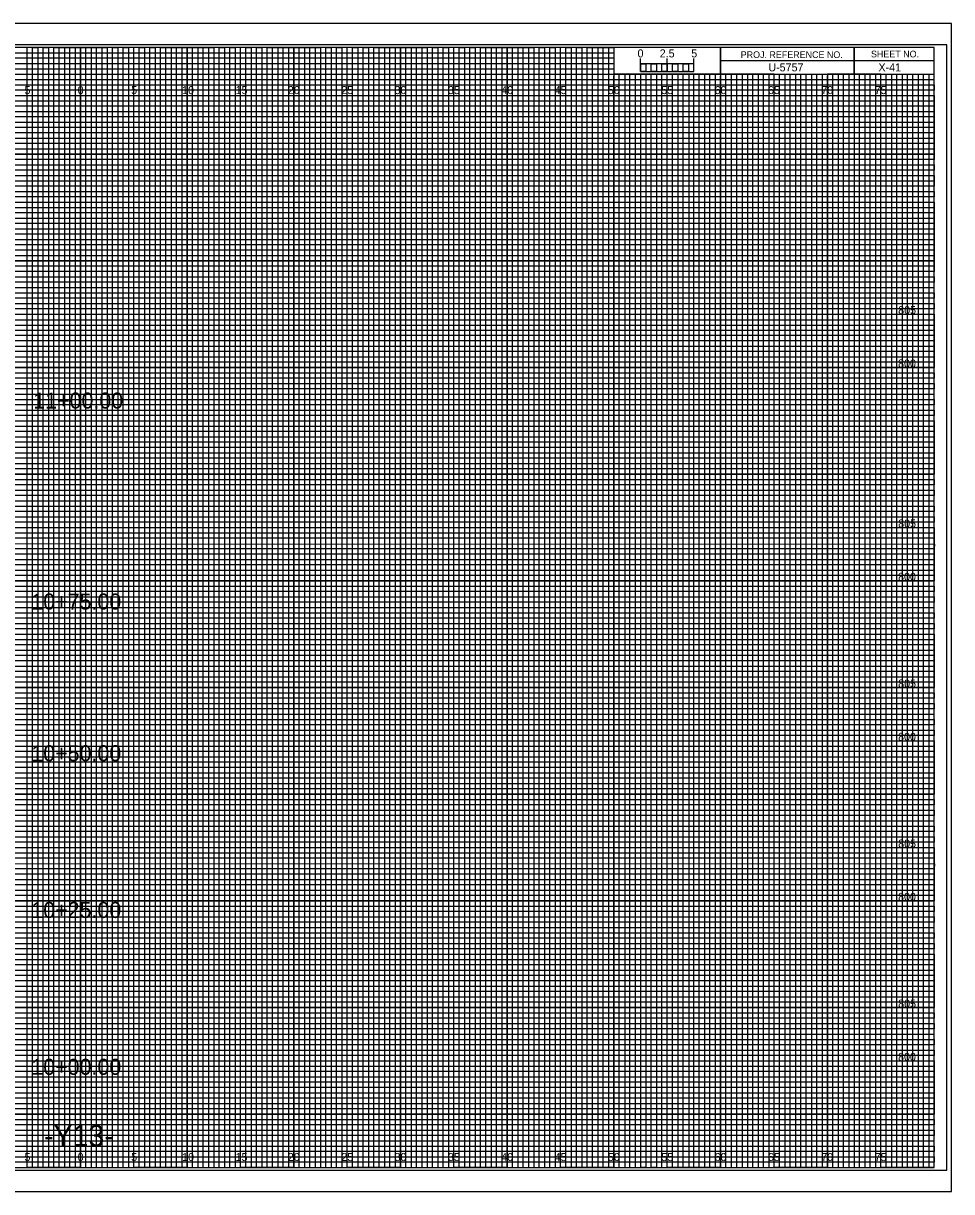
# Model space of a CAD drawing. Extents: x -7 to 162, y -2 to 107.
# Drawn here: x 74.6 to 161.7, y -2.3 to 107.3 of the extents above; entities that cross this region are included whole.
import ezdxf

# ---------------------------------------------------------------- set-up
doc = ezdxf.new("R2010")
doc.units = 0
for name, color, linetype in [('Exist CMT Pavement', 7, 'Continuous'), ('Exist Cross Section Cell', 7, 'Continuous'), ('Exist XS Center Line Elevation Label', 7, 'Continuous'), ('Prop CMT Pvmt Course 1 Wedge', 7, 'Continuous'), ('Prop CMT Pvmt Course 2 Wedge', 7, 'Continuous'), ('Prop CMT Pvmt Wedge Surface 1', 7, 'Continuous'), ('Prop XS Alignment Label', 7, 'Continuous'), ('Prop XS Bar Scale Labels', 7, 'Continuous'), ('Prop XS Hydro Elevations', 7, 'Continuous'), ('Prop XS Project Number', 7, 'Continuous'), ('Prop XS SE Text', 7, 'Continuous'), ('Prop XS Side Slope Text', 7, 'Continuous'), ('Sheet Cross Section Grid Minor 2 CELL', 7, 'Continuous'), ('Sheet Cross Section Scale CELL', 7, 'Continuous'), ('Sheet DOT Grid CELL', 7, 'Continuous'), ('Sheet Plot Border Inside CELL', 7, 'Continuous'), ('Sheet Plot Border Outside CELL', 7, 'Continuous')]:
    doc.layers.add(name, color=color, linetype=linetype)

msp = doc.modelspace()

# ---------------------------------------------------------------- linework, layer by layer
at = {"layer": 'Exist Cross Section Cell'}
for p, q in [((75, 105), (70, 105)), ((75, 0), (75, 105)), ((85, 105), (80, 105)), ((80, 105), (80, 0)), ((85, 0), (85, 105)), ((95, 105), (90, 105)), ((90, 105), (90, 0)), ((95, 0), (95, 105)), ((105, 105), (100, 105)), ((100, 105), (100, 0)), ((105, 0), (105, 105)), ((115, 105), (110, 105)), ((110, 105), (110, 0)), ((115, 0), (115, 105)), ((125, 105), (120, 105)), ((120, 105), (120, 0)), ((125, 0), (125, 105)), ((130, 105), (130, 0)), ((135, 0), (135, 102.5)), ((145, 102.5), (140, 102.5)), ((140, 102.5), (140, 0)), ((145, 0), (145, 102.5)), ((155, 102.5), (150, 102.5)), ((150, 102.5), (150, 0)), ((155, 0), (155, 102.5)), ((80, 0), (75, 0)), ((90, 0), (85, 0)), ((100, 0), (95, 0)), ((110, 0), (105, 0)), ((120, 0), (115, 0)), ((130, 0), (125, 0)), ((140, 0), (135, 0)), ((150, 0), (145, 0)), ((160, 0), (155, 0)), ((160, 0), (160, 0))]:
    msp.add_line(p, q, dxfattribs=at)
for points in [[(0, 100), (160, 100), (160, 95), (0, 95)], [(0, 90), (160, 90), (160, 85), (0, 85)], [(0, 80), (160, 80), (160, 75), (0, 75)], [(0, 70), (160, 70), (160, 65), (0, 65)], [(0, 60), (160, 60), (160, 55), (0, 55)], [(0, 50), (160, 50), (160, 45), (0, 45)], [(0, 40), (160, 40), (160, 35), (0, 35)], [(0, 30), (160, 30), (160, 25), (0, 25)], [(0, 20), (160, 20), (160, 15), (0, 15)], [(0, 10), (160, 10), (160, 5), (0, 5)]]:
    msp.add_lwpolyline(points, dxfattribs=at)
at = {"layer": 'Exist XS Center Line Elevation Label'}
for points in [[(72.5, 0), (77.5, 0), (77.5, 105), (82.5, 105), (82.5, 0), (87.5, 0), (87.5, 105), (92.5, 105), (92.5, 0), (97.5, 0), (97.5, 105), (102.5, 105), (102.5, 0), (107.5, 0), (107.5, 105), (112.5, 105), (112.5, 0), (117.5, 0), (117.5, 105), (122.5, 105), (122.5, 0), (127.5, 0), (127.5, 105), (129.97, 105), (130, 105), (130, 102.5), (132.5, 102.5), (132.5, 0), (137.5, 0), (137.5, 102.5), (142.5, 102.5), (142.5, 0), (147.5, 0), (147.5, 102.5), (152.5, 102.5), (152.5, 0), (157.5, 0), (157.5, 102.5)], [(0, 102.5), (137.5, 102.5)], [(0, 92.5), (160, 92.5), (160, 97.5), (0, 97.5)], [(0, 82.5), (160, 82.5), (160, 87.5), (0, 87.5)], [(0, 72.5), (160, 72.5), (160, 77.5), (0, 77.5)], [(0, 62.5), (160, 62.5), (160, 67.5), (0, 67.5)], [(0, 52.5), (160, 52.5), (160, 57.5), (0, 57.5)], [(0, 42.5), (160, 42.5), (160, 47.5), (0, 47.5)], [(0, 32.5), (160, 32.5), (160, 37.5), (0, 37.5)], [(0, 22.5), (160, 22.5), (160, 27.5), (0, 27.5)], [(0, 12.5), (160, 12.5), (160, 17.5), (0, 17.5)], [(0, 2.5), (160, 2.5), (160, 7.5), (0, 7.5)]]:
    msp.add_lwpolyline(points, dxfattribs=at)
at = {"layer": 'Prop CMT Pvmt Wedge Surface 1'}
for p, q in [((161.65, 107.25), (-6.7, 107.25)), ((-6.7, -2.25), (161.65, -2.25))]:
    msp.add_line(p, q, dxfattribs=at)
at = {"layer": 'Prop XS Hydro Elevations'}
for p, q in [((152.5, 105), (152.5, 102.5)), ((152.5, 102.5), (152.5, 105)), ((160, 103.75), (140, 103.75)), ((140, 103.75), (140, 102.5)), ((140, 102.5), (160, 102.5))]:
    msp.add_line(p, q, dxfattribs=at)
for points in [[(160, 105), (0, 105), (0, 0), (160, 0)], [(140, 105), (130, 105), (130, 102.52), (140, 102.52)], [(160, 105), (140, 105), (140, 102.5), (160, 102.5)]]:
    msp.add_lwpolyline(points, close=True, dxfattribs=at)
at = {"layer": 'Prop XS Side Slope Text'}
for p, q in [((0, 104.5), (130, 104.5)), ((130, 104.5), (130, 103.99)), ((130, 103.99), (0, 103.99)), ((0, 103.5), (130, 103.5)), ((130, 102.95), (0, 102.95)), ((130, 103.5), (130, 102.95)), ((0, 102), (160, 102))]:
    msp.add_line(p, q, dxfattribs=at)
for points in [[(0, 101.5), (135, 101.5), (160, 101.5), (160, 101), (0, 101)], [(0, 100.5), (160, 100.5), (160, 99.5), (0, 99.5)], [(0, 99), (160, 99), (160, 98.5), (0, 98.49)], [(0, 98), (160, 98), (160, 97), (0, 97)], [(0, 96.5), (160, 96.5), (160, 96), (0, 96)], [(0, 95.5), (160, 95.5), (160, 94.5), (0, 94.5)], [(0, 94), (160, 94), (160, 93.5), (0, 93.5)], [(0, 93), (160, 93), (160, 92), (0, 92)], [(0, 91.5), (160, 91.5), (160, 91), (0, 91)], [(0, 90.5), (160, 90.5), (160, 89.5), (0, 89.5)], [(0, 89), (160, 89), (160, 88.5), (0, 88.5)], [(0, 88), (160, 88), (160, 86.98), (160, 86.5), (160, 86), (0, 86)], [(0, 87), (160, 87), (160, 86.5), (0, 86.5)], [(0, 85.5), (160, 85.5), (160, 84.5), (0, 84.52)], [(0, 84.52), (160, 84.5), (160, 84), (0, 84)], [(0, 83.5), (160, 83.5), (160, 83), (0, 83)], [(0, 82), (160, 82), (160, 81.5), (0, 81.5)], [(0, 81), (160, 81), (160, 80.5), (0, 80.5)], [(-0.04, 79.45), (160, 79.45), (160, 78.94), (-0.04, 78.94)], [(0, 78.5), (160, 78.5), (160, 78), (0, 78)], [(0, 77), (160, 77), (160, 76.5), (0, 76.5)], [(0, 76), (160, 76), (160, 75.5), (0, 75.5)], [(0, 74.5), (160, 74.5), (160, 74), (0, 74)], [(0, 73.5), (160, 73.5), (160, 73), (0, 73)], [(0, 72), (160, 72), (160, 71.5), (0, 71.5)], [(0, 71), (160, 71), (160, 70.5), (0, 70.5)], [(0, 69.5), (160, 69.5), (160, 68.99), (0, 69)], [(0, 68.5), (160, 68.5), (160, 68), (0, 68)], [(0, 67), (160, 67), (160, 66.5), (0, 66.5)], [(0, 66), (160, 66), (160, 65.5), (0, 65.5)], [(0, 64.5), (160, 64.5), (160, 64), (0, 64)], [(0, 63.5), (160, 63.5), (160, 63), (0, 63)], [(0, 62), (160, 62), (160, 61.5), (0, 61.5)], [(0, 61), (160, 61), (160, 60.5), (0, 60.5)], [(0, 59.5), (160, 59.5), (160, 59), (0, 59)], [(0, 58.5), (160.03, 58.45), (160, 58), (0, 58)], [(0, 57), (160, 57), (160, 56.5), (0, 56.5)], [(0, 56), (160, 56), (160, 55.5), (0, 55.5)], [(0, 54.5), (160, 54.5), (160, 54), (0, 54)], [(0, 53.5), (160, 53.5), (160, 53), (0, 53)], [(0, 52), (160, 52), (160, 51.5), (0, 51.5)], [(0, 51), (160, 51), (160, 50.5), (0, 50.5)], [(0, 49.5), (160, 49.5), (160, 49), (0, 49)], [(0, 48.5), (160, 48.5), (160, 48), (0, 48)], [(0, 47), (160, 47), (160, 46.5), (0, 46.5)], [(0, 46), (160, 46), (160, 45.5), (0, 45.5)], [(0, 44.5), (160, 44.5), (160, 44), (0, 44)], [(0, 43.5), (160, 43.5), (160, 43), (0, 43)], [(0, 42), (160, 42), (160, 41.5), (0, 41.5)], [(0, 41), (160, 41), (160, 40.5), (0, 40.5)], [(0, 39.5), (160, 39.5), (160, 38.99), (0, 39)], [(0, 38.5), (160, 38.5), (160, 38), (0, 38)], [(0, 37), (160, 37), (160, 36.5), (0, 36.5)], [(0, 36), (160, 36), (160, 35.5), (0, 35.5)], [(0, 34.5), (160, 34.5), (160, 34), (0, 34)], [(0, 33.5), (160, 33.5), (160, 33), (0, 33)], [(0, 32), (160, 32), (160, 31.5), (0, 31.5)], [(0, 31), (160, 31), (160, 30.5), (0, 30.5)], [(0, 29.5), (160, 29.5), (160, 29), (0, 29)], [(0, 28.5), (160.03, 28.46), (160, 28), (0, 28)], [(0, 27), (160, 27), (160, 26.5), (0, 26.5)], [(0, 26), (160, 26), (160, 25.5), (0, 25.5)], [(0, 24.5), (160, 24.5), (160, 24), (0, 24)], [(0, 23.5), (160, 23.5), (160, 23), (0, 23)], [(0, 22), (160, 22), (160, 21.5), (0, 21.5)], [(0, 21), (160, 21), (160, 20.5), (0, 20.5)], [(0, 19.5), (160, 19.5), (160, 19), (0, 19)], [(0, 18.5), (160, 18.5), (160, 18), (0, 18)], [(0, 17), (160, 17), (160, 16.5), (0, 16.5)], [(0, 16), (160, 16), (160, 15.5), (0, 15.5)], [(0, 14.5), (160, 14.5), (160, 14), (0, 14)], [(0, 13.5), (160, 13.5), (160, 13), (0, 13)], [(0, 12), (160, 12), (160, 11.5), (0, 11.5)], [(0, 11), (160, 11), (160, 10.5), (0, 10.5)], [(0, 9.5), (160, 9.5), (160, 9), (0, 9)], [(0, 8.5), (160, 8.5), (160, 8), (0, 8)], [(0, 7), (160, 7), (160, 6.5), (0, 6.5)], [(0, 6), (160, 6), (160, 5.5), (0, 5.5)], [(0, 4.5), (160, 4.5), (160, 4), (0, 4)], [(0, 3.5), (160, 3.5), (160, 3), (0, 3)], [(0, 2), (160, 2), (160, 1.5), (0, 1.5)], [(0, 1), (160, 1), (160, 0.5), (0, 0.5)]]:
    msp.add_lwpolyline(points, dxfattribs=at)
at = {"layer": 'Sheet Cross Section Grid Minor 2 CELL'}
for p, q in [((133.5, 102.5), (133, 102.5)), ((133, 102.5), (133, 0)), ((133.5, 0), (133.5, 102.5)), ((134.5, 102.5), (134, 102.5)), ((134, 102.5), (134, 0)), ((134.5, 0), (134.5, 102.5)), ((133, 0), (132.5, 0)), ((134, 0), (133.5, 0))]:
    msp.add_line(p, q, dxfattribs=at)
for points in [[(75, 0), (75.5, 0), (75.5, 105), (76, 105), (76, 0)], [(76, 0), (76.5, 0), (76.5, 105), (77, 105), (77, 0)], [(77.5, 0), (78, 0), (78, 105), (78.5, 105), (78.5, 0)], [(78.5, 0), (79, 0), (79, 105), (79.5, 105), (79.5, 0)], [(80, 0), (80.5, 0), (80.5, 105), (81, 105), (81, 0)], [(81, 0), (81.5, 0), (81.5, 105), (82, 105), (82, 0)], [(82.5, 0), (83, 0), (83, 105), (83.5, 105), (83.5, 0)], [(83.5, 0), (84, 0), (84, 105), (84.5, 105), (84.5, 0)], [(85, 0), (85.5, 0), (85.5, 105), (86, 105), (86, 0)], [(86, 0), (86.5, 0), (86.5, 105), (87, 105), (87, 0)], [(87.5, 0), (88, 0), (88, 105), (88.5, 105), (88.5, 0)], [(88.5, 0), (89, 0), (89, 105), (89.5, 105), (89.5, 0)], [(90, 0), (90.5, 0), (90.5, 105), (91, 105), (91, 0)], [(91, 0), (91.5, 0), (91.5, 105), (92, 105), (92, 0)], [(92.5, 0), (93, 0), (93, 105), (93.5, 105), (93.5, 0)], [(93.5, 0), (94, 0), (94, 105), (94.5, 105), (94.5, 0)], [(95, 0), (95.5, 0), (95.5, 105), (96, 105), (96, 0)], [(96, 0), (96.5, 0), (96.5, 105), (97, 105), (97, 0)], [(97.5, 0), (98, 0), (98, 105), (98.5, 105), (98.5, 0)], [(98.5, 0), (99, 0), (99, 105), (99.5, 105), (99.5, 0)], [(100, 0), (100.5, 0), (100.5, 105), (101, 105), (101, 0)], [(101, 0), (101.5, 0), (101.5, 105), (102, 105), (102, 0)], [(102.5, 0), (103, 0), (103, 105), (103.5, 105), (103.5, 0)], [(103.5, 0), (104, 0), (104, 105), (104.5, 105), (104.5, 0)], [(105, 0), (105.5, 0), (105.5, 105), (106, 105), (106, 0)], [(106, 0), (106.5, 0), (106.5, 105), (107, 105), (107, 0)], [(107.5, 0), (108, 0), (108, 105), (108.5, 105), (108.5, 0)], [(108.5, 0), (109, 0), (109, 105), (109.5, 105), (109.5, 0)], [(110, 0), (110.5, 0), (110.5, 105), (111, 105), (111, 0)], [(111, 0), (111.5, 0), (111.5, 105), (112, 105), (112, 0)], [(112.5, 0), (113, 0), (113, 105), (113.5, 105), (113.5, 0)], [(113.5, 0), (114, 0), (114, 105), (114.5, 105), (114.5, 0)], [(115, 0), (115.5, 0), (115.5, 105), (116, 105), (116, 0)], [(116, 0), (116.5, 0), (116.5, 105), (117, 105), (117, 0)], [(117.5, 0), (118, 0), (118, 105), (118.5, 105), (118.5, 0)], [(118.5, 0), (119, 0), (119, 105), (119.5, 105), (119.5, 0)], [(120, 0), (120.5, 0), (120.5, 105), (121, 105), (121, 0)], [(121, 0), (121.5, 0), (121.5, 105), (122, 105), (122, 0)], [(122.5, 0), (123, 0), (123, 105), (123.5, 105), (123.5, 0)], [(123.5, 0), (124, 0), (124, 105), (124.5, 105), (124.5, 0)], [(125, 0), (125.5, 0), (125.5, 105), (126, 105), (126, 0)], [(126, 0), (126.5, 0), (126.5, 105), (127, 105), (127, 0)], [(127.5, 0), (128, 0), (128, 105), (128.5, 105), (128.5, 0)], [(128.5, 0), (129, 0), (129, 105), (129.5, 105), (129.5, 0)], [(130, 0), (130.5, 0), (130.5, 102.5), (131.01, 102.5), (131.01, 0)], [(131, 0), (131.5, 0), (131.5, 102.5), (132, 102.5), (132, 0)], [(135, 0), (135.49, 0), (135.49, 102.5), (136, 102.5), (136, 0)], [(136, 0), (136.5, 0), (136.5, 102.5), (137.03, 102.5), (137.03, 0)], [(137.5, 0), (138, 0), (138, 102.5), (138.5, 102.5), (138.5, 0)], [(138.5, 0), (139, 0), (139, 102.5), (139.5, 102.5), (139.5, 0)], [(140, 0), (140.5, 0), (140.5, 102.5), (141, 102.5), (141, 0)], [(141, 0), (141.5, 0), (141.5, 102.5), (142, 102.5), (142, 0)], [(142.5, 0), (143, 0), (143, 102.5), (143.5, 102.5), (143.5, 0)], [(143.5, 0), (144, 0), (144, 102.5), (144.5, 102.5), (144.5, 0)], [(145, 0), (145.5, 0), (145.5, 102.5), (146, 102.5), (146, 0)], [(146, 0), (146.5, 0), (146.5, 102.5), (147, 102.5), (147, 0)], [(147.5, 0), (148, 0), (148, 102.5), (148.5, 102.5), (148.5, 0)], [(148.5, 0), (149, 0), (149, 102.5), (149.5, 102.5), (149.5, 0)], [(150, 0), (150.5, 0), (150.5, 102.5), (151, 102.5), (151, 0)], [(151, 0), (151.5, 0), (151.5, 102.5), (152, 102.5), (152, 0)], [(152.5, 0), (153, 0), (153, 102.5), (153.5, 102.5), (153.5, 0)], [(153.5, 0), (154, 0), (154, 102.5), (154.5, 102.5), (154.5, 0)], [(155, 0), (155.5, 0), (155.5, 102.5), (156, 102.5), (156, 0)], [(156, 0), (156.5, 0), (156.5, 102.5), (157, 102.5), (157, 0)], [(157.5, 0), (158, 0), (158, 102.5), (158.5, 102.5), (158.5, 0)], [(158.5, 0), (159, 0), (159, 102.5), (159.5, 102.5), (159.5, 0)]]:
    msp.add_lwpolyline(points, dxfattribs=at)
at = {"layer": 'Sheet Cross Section Scale CELL'}
for p, q in [((132.5, 102.75), (132.5, 103.95)), ((132.5, 103.45), (132.5, 103.95)), ((135, 102.75), (135, 103.95)), ((137.5, 102.75), (137.5, 103.95)), ((137.5, 103.45), (137.5, 103.95))]:
    msp.add_line(p, q, dxfattribs=at)
for points in [[(137.5, 103.45), (132.5, 103.45), (132.5, 102.75), (137.5, 102.75)], [(132.5, 103.45), (133, 103.45), (133, 102.75), (132.5, 102.75)], [(133.5, 103.45), (134, 103.45), (134, 102.75), (133.5, 102.75)], [(134.5, 103.45), (135, 103.45), (135, 102.75), (134.5, 102.75)], [(135.5, 103.45), (136, 103.45), (136, 102.75), (135.5, 102.75)], [(136.5, 103.45), (137, 103.45), (137, 102.75), (136.5, 102.75)]]:
    msp.add_lwpolyline(points, close=True, dxfattribs=at)
at = {"layer": 'Sheet DOT Grid CELL'}
for p, q in [((75, 0), (75, 105)), ((80, 0), (80, 105)), ((85, 0), (85, 105)), ((90, 0), (90, 105)), ((95, 0), (95, 105)), ((100, 0), (100, 105)), ((105, 0), (105, 105)), ((110, 0), (110, 105)), ((115, 0), (115, 105)), ((120, 0), (120, 105)), ((125, 0), (125, 105)), ((130, 0), (130, 102.34)), ((135, 0), (135, 102.34)), ((140, 0), (140, 102.34)), ((145, 0), (145, 102.34)), ((150, 0), (150, 102.34)), ((155, 0), (155, 102.34)), ((0, 100), (160, 100)), ((0, 95), (160, 95)), ((0, 90), (160, 90)), ((0, 85), (160, 85)), ((0, 80), (160, 80)), ((0, 75), (160, 75)), ((0, 70), (160, 70)), ((0, 65), (160, 65)), ((0, 60), (160, 60)), ((0, 55), (160, 55)), ((0, 50), (160, 50)), ((0, 45), (160, 45)), ((0, 40), (160, 40)), ((0, 35), (160, 35)), ((0, 30), (160, 30)), ((0, 25), (160, 25)), ((0, 20), (160, 20)), ((0, 15), (160, 15)), ((0, 10), (160, 10)), ((0, 5), (160, 5))]:
    msp.add_line(p, q, dxfattribs=at)
at = {"layer": 'Sheet Plot Border Inside CELL'}
msp.add_lwpolyline([(-5.4, -0.25), (161.2, -0.25), (161.2, 105.25), (-5.4, 105.25)], close=True, dxfattribs=at)
at = {"layer": 'Sheet Plot Border Outside CELL'}
msp.add_lwpolyline([(-6.7, -2.25), (161.65, -2.25), (161.65, 107.25), (-6.7, 107.25)], close=True, dxfattribs=at)

# ---------------------------------------------------------------- texts
at = {"layer": 'Exist CMT Pavement'}
msp.add_text('X-41', height=0.75, dxfattribs=at).set_placement((154.79, 102.75))
at = {"layer": 'Prop CMT Pvmt Course 1 Wedge'}
for s, p in [('805', (156.64, 80)), ('800', (156.63, 75)), ('805', (156.64, 60)), ('800', (156.63, 55)), ('805', (156.64, 45)), ('800', (156.63, 40)), ('805', (156.64, 30)), ('800', (156.63, 25)), ('805', (156.64, 15)), ('800', (156.63, 10))]:
    msp.add_text(s, height=0.75, dxfattribs=at).set_placement(p)
at = {"layer": 'Prop CMT Pvmt Course 2 Wedge'}
for s, p in [('11+00.00', (75.57, 71.15)), ('10+75.00', (75.39, 52.31)), ('10+50.00', (75.39, 38.09)), ('10+25.00', (75.39, 23.4)), ('10+00.00', (75.39, 8.7))]:
    msp.add_text(s, height=1.5, dxfattribs=at).set_placement(p)
at = {"layer": 'Prop XS Alignment Label'}
msp.add_text('-Y13-', height=2, dxfattribs=at).set_placement((76.57, 2))
at = {"layer": 'Prop XS Bar Scale Labels'}
for s, p in [('2.5', (134.29, 104.06)), ('5', (137.24, 104.06))]:
    msp.add_text(s, height=0.75, dxfattribs=at).set_placement(p)
at = {"layer": 'Prop XS Hydro Elevations'}
for s, p in [('PROJ. REFERENCE NO.', (141.88, 104)), ('SHEET NO.', (154.09, 104.06))]:
    msp.add_text(s, height=0.625, dxfattribs=at).set_placement(p)
at = {"layer": 'Prop XS Project Number'}
msp.add_text('U-5757', height=0.75, dxfattribs=at).set_placement((144.47, 102.75))
at = {"layer": 'Prop XS SE Text'}
for s, p in [('5', (74.74, 100.62)), ('0', (79.73, 100.62)), ('0', (79.73, 100.62)), ('5', (84.74, 100.62)), ('10', (89.52, 100.62)), ('15', (94.53, 100.62)), ('20', (99.43, 100.62)), ('25', (104.44, 100.62)), ('30', (109.43, 100.62)), ('35', (114.44, 100.62)), ('40', (119.43, 100.62)), ('45', (124.44, 100.62)), ('50', (129.43, 100.62)), ('55', (134.44, 100.62)), ('60', (139.43, 100.62)), ('65', (144.44, 100.62)), ('70', (149.43, 100.62)), ('75', (154.44, 100.62)), ('5', (74.74, 0.62)), ('0', (79.73, 0.62)), ('0', (79.73, 0.62)), ('5', (84.74, 0.62)), ('10', (89.52, 0.62)), ('15', (94.53, 0.62)), ('20', (99.43, 0.62)), ('25', (104.44, 0.62)), ('30', (109.43, 0.62)), ('35', (114.44, 0.62)), ('40', (119.43, 0.62)), ('45', (124.44, 0.62)), ('50', (129.43, 0.62)), ('55', (134.44, 0.62)), ('60', (139.43, 0.62)), ('65', (144.44, 0.62)), ('70', (149.43, 0.62)), ('75', (154.44, 0.62))]:
    msp.add_text(s, height=0.75, dxfattribs=at).set_placement(p)
at = {"layer": 'Sheet Cross Section Scale CELL'}
msp.add_text('0', height=0.75, dxfattribs=at).set_placement((132.21, 104.06))

doc.saveas('drawing.dxf')
